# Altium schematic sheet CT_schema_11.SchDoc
size 274 x 160 mm
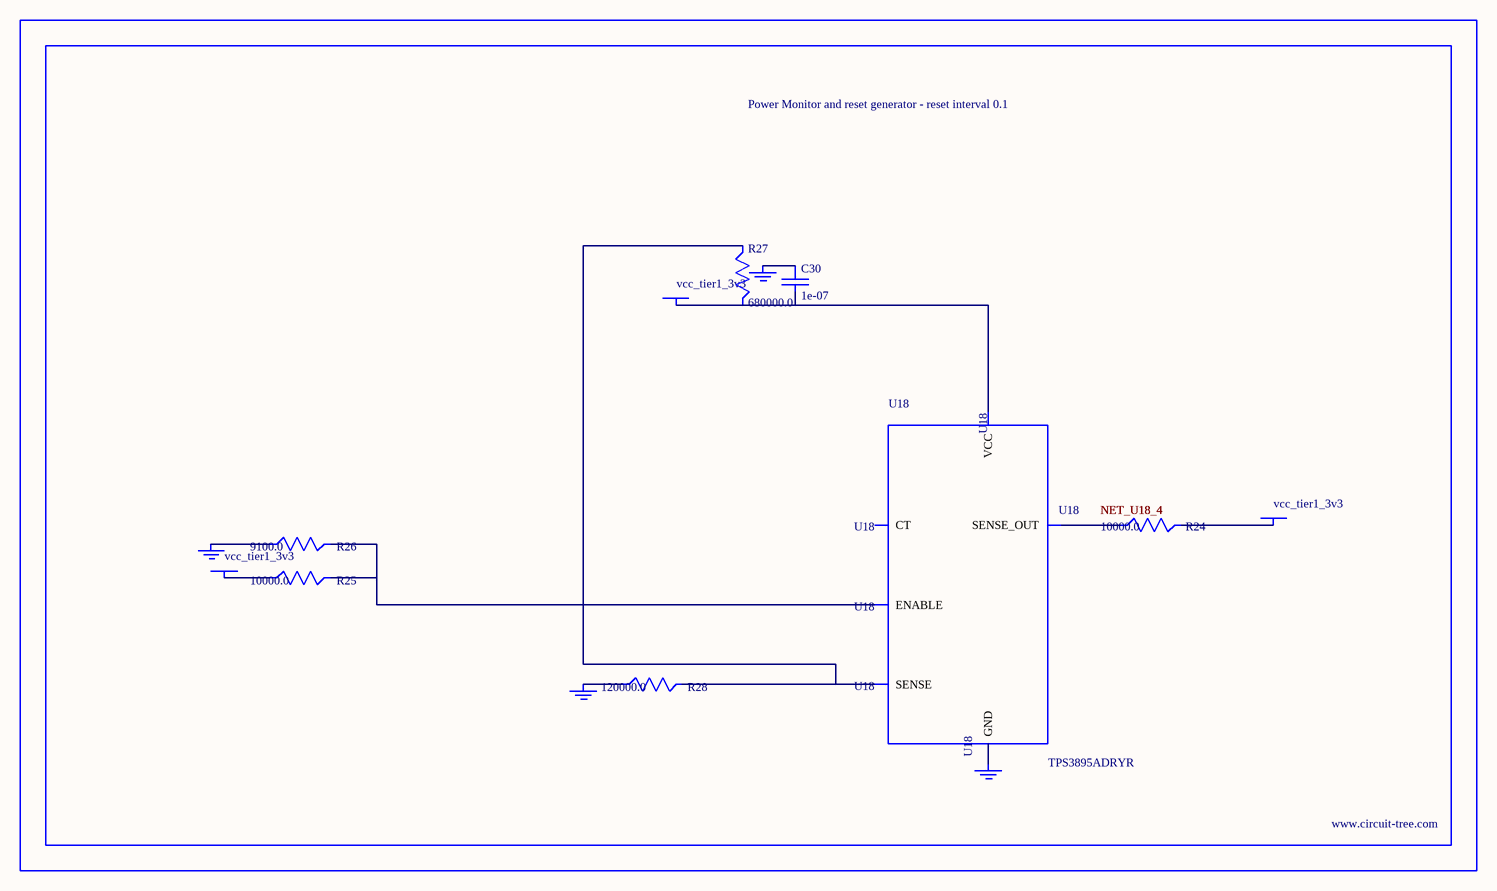
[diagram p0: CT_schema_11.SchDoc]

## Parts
BORDER10  (no value)
C30  1e-07  [C0402]
GND_INSTANCE_10_0  (no value)
GND_INSTANCE_10_1  (no value)
GND_INSTANCE_10_2  (no value)
GND_INSTANCE_10_3  (no value)
POWER_INSTANCE_10_0  vcc_tier1_3v3
POWER_INSTANCE_10_1  vcc_tier1_3v3
POWER_INSTANCE_10_2  vcc_tier1_3v3
R24  10000.0  [R0603]
R25  10000.0  [R0603]
R26  9100.0  [R0603]
R27  680000.0  [R0603]
R28  120000.0  [R0603]
U18  TPS3895ADRYR  [SON-6]

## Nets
NetC30_1: C30.1 GND_INSTANCE_10_2.0(GND)
NetC30_2: C30.2 POWER_INSTANCE_10_2.0(PWR) R27.2 U18.6(VCC)
NetGND_INSTANCE_10_0_0: GND_INSTANCE_10_0.0(GND) R26.1
NetGND_INSTANCE_10_1_0: GND_INSTANCE_10_1.0(GND) R28.1
NetGND_INSTANCE_10_3_0: GND_INSTANCE_10_3.0(GND) U18.2(GND)
NetPOWER_INSTANCE_10_0_0: POWER_INSTANCE_10_0.0(PWR) R25.1
NetPOWER_INSTANCE_10_1_0: POWER_INSTANCE_10_1.0(PWR) R24.2
NetR24_1: R24.1 U18.4(SENSE_OUT)
NetR25_2: R25.2 R26.2 U18.1(ENABLE)
NetR27_1: R27.1 R28.2 U18.3(SENSE)

Not connected (* = marked no-connect by the designer): U18 5(CT)

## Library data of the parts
BORDER10 = BORDER_PAGE10
C30 = C0402C104K3RACTU
GND_INSTANCE_10_0-GND_INSTANCE_10_3 = GND
POWER_INSTANCE_10_0-POWER_INSTANCE_10_2 = PWR
R24 R25 = RC0603JR-0710KL
R26 = RC0603JR-079K1L
R27 = RC0603JR-07680KL
R28 = RC0603JR-07120KL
